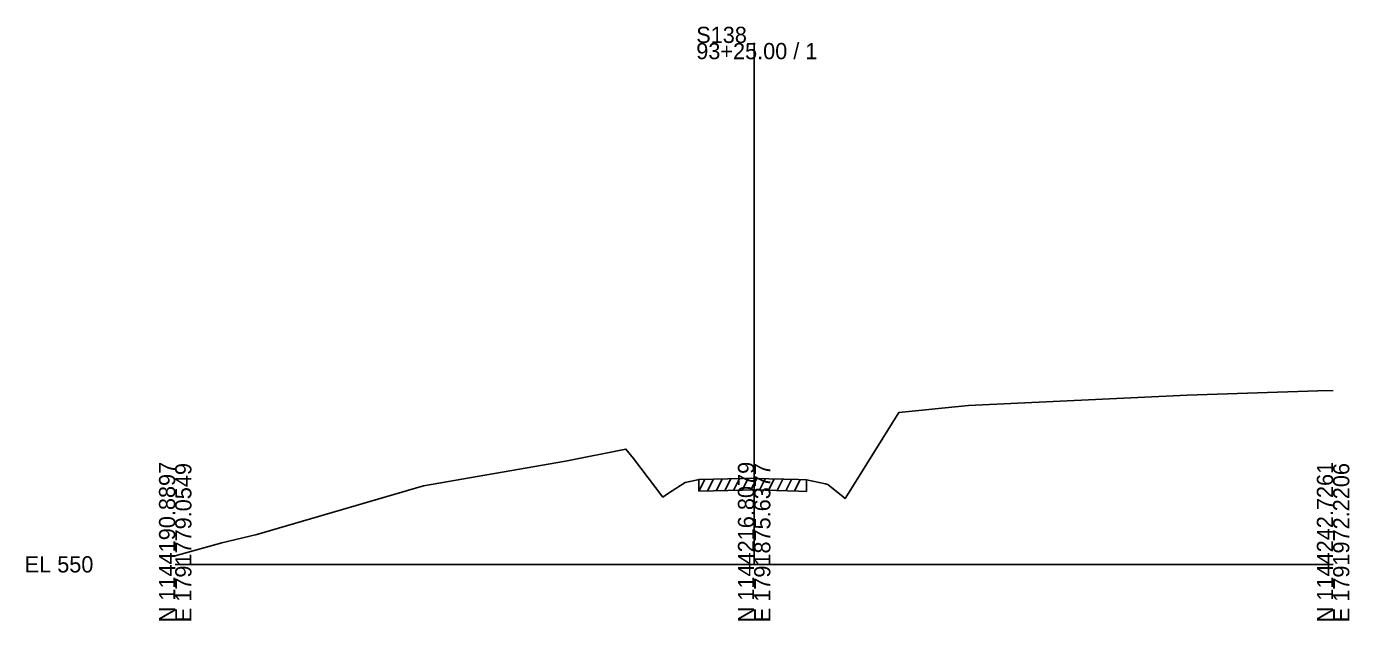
# Model space of a CAD drawing. Extents: x -26 to 1203, y -10 to 19606.
# Drawn here: x 974.3 to 1202.8, y 6490.3 to 6592.8 of the extents above; entities that cross this region are included whole.
import ezdxf

# ---------------------------------------------------------------- set-up
doc = ezdxf.new("R2010")
doc.units = 0
for name, color, linetype in [('RD_EX_Driveway', 7, 'Continuous'), ('RD_GPK_XS_Cell', 7, 'Continuous'), ('RD_XS_ExGround', 7, 'Continuous'), ('RD_XS_ExPaveRet', 7, 'Continuous')]:
    doc.layers.add(name, color=color, linetype=linetype)

msp = doc.modelspace()

# ---------------------------------------------------------------- linework, layer by layer
at = {"layer": 'RD_GPK_XS_Cell'}
for p, q in [((1100, 6500), (1100, 6589.98)), ((1000, 6500), (1100, 6500)), ((1100, 6500), (1200, 6500))]:
    msp.add_line(p, q, dxfattribs=at)
at = {"layer": 'RD_XS_ExGround'}
msp.add_lwpolyline([(1000, 6501.45), (1008.08, 6503.72), (1014.12, 6505.16), (1042.89, 6513.55), (1067.39, 6517.82), (1077.86, 6519.88), (1079.14, 6518.29), (1084.25, 6511.61), (1085.04, 6512.17), (1088.1, 6514.14), (1089.96, 6514.54), (1090.45, 6514.65), (1098.01, 6514.8), (1099.51, 6514.85), (1100, 6514.84), (1107.66, 6514.63), (1109.03, 6514.59), (1112.3, 6513.87), (1112.75, 6513.77), (1115.35, 6511.64), (1115.7, 6511.36), (1116.72, 6512.92), (1125, 6526.21), (1137.04, 6527.43), (1174.82, 6529.19), (1197.35, 6529.96), (1200, 6529.99)], dxfattribs=at)
at = {"layer": 'RD_XS_ExPaveRet'}
for p, q in [((1090.45, 6512.65), (1091.46, 6514.67)), ((1090.45, 6512.65), (1090.45, 6514.65)), ((1091.95, 6512.68), (1092.96, 6514.7)), ((1093.45, 6512.71), (1094.46, 6514.73)), ((1094.95, 6512.74), (1095.96, 6514.76)), ((1096.45, 6512.77), (1097.46, 6514.79)), ((1097.95, 6512.8), (1098.96, 6514.83)), ((1099.45, 6512.85), (1100.44, 6514.82)), ((1100.95, 6512.81), (1101.93, 6514.78)), ((1102.45, 6512.77), (1103.43, 6514.74)), ((1103.95, 6512.73), (1104.93, 6514.7)), ((1105.45, 6512.69), (1106.43, 6514.66)), ((1106.95, 6512.65), (1107.93, 6514.62)), ((1109.03, 6514.59), (1109.03, 6512.59)), ((1090.45, 6512.65), (1098.01, 6512.8)), ((1098.01, 6512.8), (1099.51, 6512.85)), ((1099.51, 6512.85), (1100, 6512.84)), ((1100, 6512.84), (1107.66, 6512.63)), ((1107.66, 6512.63), (1109.03, 6512.59))]:
    msp.add_line(p, q, dxfattribs=at)

# ---------------------------------------------------------------- texts
at = {"layer": 'RD_EX_Driveway'}
msp.add_text('557.42', height=0.0975, rotation=90, dxfattribs=at).set_placement((1100.1, 6514.84))
at = {"layer": 'RD_GPK_XS_Cell'}
for s, p in [('S138', (1090, 6589.98)), ('93+25.00 / 1', (1090, 6587.18)), ('EL 550', (974, 6498.6))]:
    msp.add_text(s, height=2.8, dxfattribs=at).set_placement(p)
for s, p in [('N 1144190.8897', (1000, 6490)), ('E 1791779.0549', (1002.8, 6490)), ('N 1144216.8079', (1100, 6490)), ('E 1791875.6377', (1102.8, 6490)), ('N 1144242.7261', (1200, 6490)), ('E 1791972.2206', (1202.8, 6490))]:
    msp.add_text(s, height=2.8, rotation=90, dxfattribs=at).set_placement(p)

doc.saveas('drawing.dxf')
